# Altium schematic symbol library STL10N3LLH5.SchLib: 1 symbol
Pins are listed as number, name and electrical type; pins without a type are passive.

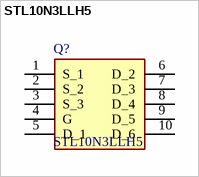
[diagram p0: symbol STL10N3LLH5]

## STL10N3LLH5
designator Q?
STMICROELECTRONICS - STL10N3LLH5 - MOSFET, N-CH, 30V, 9A, POWERFLAT; Geometry.Height: 1mm
footprint STL10N3LLH5
pins: 1 S_1, 2 S_2, 3 S_3, 4 G, 5 D_1, 6 D_2, 7 D_3, 8 D_4, 9 D_5, 10 D_6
